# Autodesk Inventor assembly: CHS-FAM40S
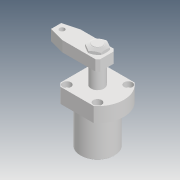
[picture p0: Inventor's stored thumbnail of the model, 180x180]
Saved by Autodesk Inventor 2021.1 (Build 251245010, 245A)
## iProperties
Created: 2019-04
Part Number: CHS-FAM40S
Description: STEP AP203
Document SubType Name: Assembly
Designer: user
Title: chs-fam40s_asm.STEP
Revision Number: ÈÎºÎ
Sending System: SolidWorks 2017
Preprocessor: SwSTEP 2.0
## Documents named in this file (5)
- D:\Vault_2016\Projekty\Clamptek\Hydraulic\CHS\CHS-40\Inventor\CHS-FAM40S\CHS-FAM40S.iam
- D:\Vault_2016\Projekty\Clamptek\Hydraulic\CHS\CHS-40\Inventor\CHS-FAM40S\CHS-FAM40-03_1.ipt
- D:\Vault_2016\Projekty\Clamptek\Hydraulic\CHS\CHS-40\Inventor\CHS-FAM40S\CHS-40S-02_2.ipt
- D:\Vault_2016\Projekty\Clamptek\Hydraulic\CHS\CHS-40\Inventor\CHS-FAM40S\CHS-40S-01_2.ipt
- D:\Vault_2016\Projekty\Clamptek\Hydraulic\CHS\CHS-40\Inventor\CHS-FAM40S\M18_2.ipt
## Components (4 placed, 4 different names)
1. CHS-FAM40-03_1_1
2. CHS-40S-02_2_2
3. CHS-40S-01_2_3
4. M18_2_4
